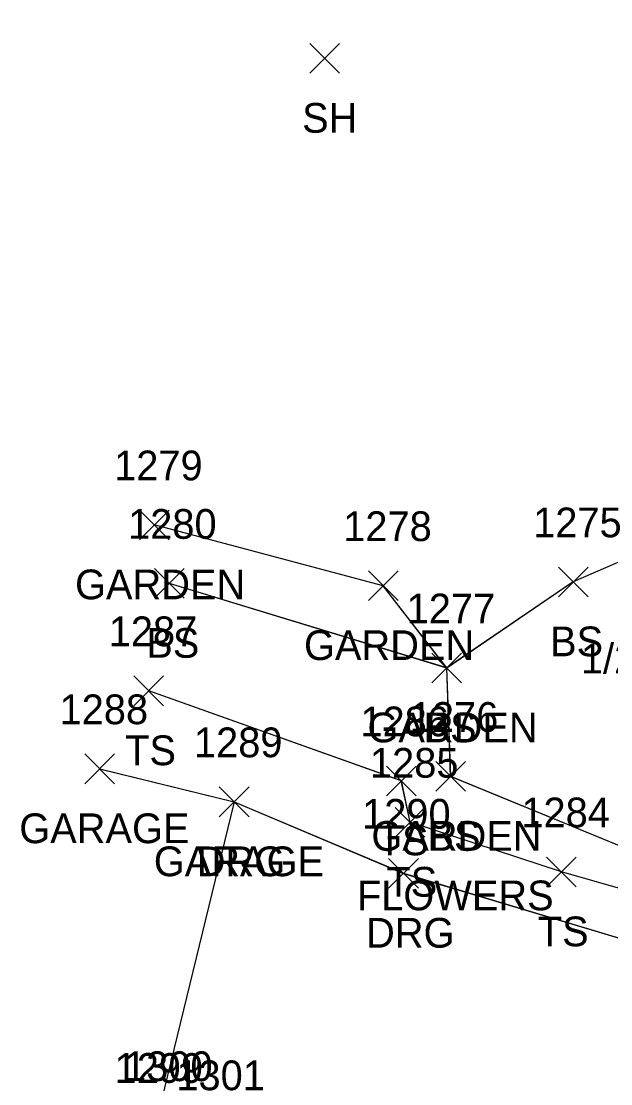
# Model space of a CAD drawing. Extents: x 1554668 to 1563881, y 831386 to 834374.
# Drawn here: x 1561770.7 to 1561810.3, y 833607.6 to 833679 of the extents above; entities that cross this region are included whole.
import ezdxf

# ---------------------------------------------------------------- set-up
doc = ezdxf.new("R2010")
doc.units = 0
for name, color, linetype in [('L_A', 7, 'Continuous'), ('L_C', 7, 'Continuous'), ('L_I', 7, 'Continuous'), ('L_TIC', 7, 'Continuous'), ('LAPB', 7, 'Continuous'), ('LBC', 7, 'Continuous'), ('LELB', 7, 'Continuous'), ('M_C', 7, 'Continuous'), ('R_A', 7, 'Continuous'), ('R_I', 7, 'Continuous'), ('R_TIC', 7, 'Continuous'), ('RDG', 7, 'Continuous')]:
    doc.layers.add(name, color=color, linetype=linetype)

msp = doc.modelspace()

# ---------------------------------------------------------------- linework, layer by layer
at = {"layer": 'L_TIC'}
for points in [[(1561790.057, 833675.514), (1561792.057, 833677.514)], [(1561792.057, 833675.514), (1561790.057, 833677.514)], [(1561778.611, 833644.139), (1561780.611, 833646.139)], [(1561780.611, 833644.139), (1561778.611, 833646.139)], [(1561806.77, 833640.307), (1561808.77, 833642.307)], [(1561808.77, 833640.307), (1561806.77, 833642.307)], [(1561779.627, 833640.207), (1561781.627, 833642.207)], [(1561781.627, 833640.207), (1561779.627, 833642.207)], [(1561794.002, 833640.053), (1561796.002, 833642.053)], [(1561796.002, 833640.053), (1561794.002, 833642.053)], [(1561798.266, 833634.519), (1561800.266, 833636.519)], [(1561800.266, 833634.519), (1561798.266, 833636.519)], [(1561798.266, 833634.519), (1561800.266, 833636.519)], [(1561800.266, 833634.519), (1561798.266, 833636.519)], [(1561778.239, 833632.983), (1561780.239, 833634.983)], [(1561780.239, 833632.983), (1561778.239, 833634.983)], [(1561774.934, 833627.739), (1561776.934, 833629.739)], [(1561776.934, 833627.739), (1561774.934, 833629.739)], [(1561795.213, 833626.925), (1561797.213, 833628.925)], [(1561797.213, 833626.925), (1561795.213, 833628.925)], [(1561798.53, 833627.225), (1561800.53, 833629.225)], [(1561800.53, 833627.225), (1561798.53, 833629.225)], [(1561798.53, 833627.225), (1561800.53, 833629.225)], [(1561800.53, 833627.225), (1561798.53, 833629.225)], [(1561783.977, 833625.518), (1561785.977, 833627.518)], [(1561785.977, 833625.518), (1561783.977, 833627.518)], [(1561795.8, 833624.141), (1561797.8, 833626.141)], [(1561797.8, 833624.141), (1561795.8, 833626.141)], [(1561805.977, 833620.804), (1561807.977, 833622.804)], [(1561807.977, 833620.804), (1561805.977, 833622.804)]]:
    msp.add_lwpolyline(points, dxfattribs=at)
at = {"layer": 'LAPB'}
for points in [[(1561799.534, 833628.228), (1561799.263, 833635.518), (1561795.003, 833641.053), (1561779.611, 833645.139)], [(1561799.534, 833628.228), (1561799.263, 833635.518), (1561795.003, 833641.053), (1561779.611, 833645.139)], [(1561799.534, 833628.228), (1561799.263, 833635.518), (1561795.003, 833641.053), (1561779.611, 833645.139)], [(1561799.53, 833628.225), (1561799.266, 833635.519), (1561795.002, 833641.053), (1561779.611, 833645.139)]]:
    msp.add_lwpolyline(points, dxfattribs=at)
at = {"layer": 'LBC'}
for points in [[(1561775.934, 833628.739), (1561784.977, 833626.518), (1561779.645, 833604.619), (1561778.909, 833601.945)], [(1561775.938, 833628.741), (1561784.978, 833626.518), (1561779.644, 833604.618), (1561778.911, 833601.947)], [(1561775.938, 833628.741), (1561784.978, 833626.518), (1561779.644, 833604.618), (1561778.911, 833601.947)], [(1561775.938, 833628.741), (1561784.978, 833626.518), (1561779.644, 833604.618), (1561778.911, 833601.947)]]:
    msp.add_lwpolyline(points, dxfattribs=at)
at = {"layer": 'LELB'}
for points in [[(1561848.403, 833772.22), (1561859.088, 833762.967), (1561862.218, 833760.08), (1561856.867, 833725.001), (1561850.329, 833695.923), (1561848.444, 833676.048), (1561846.147, 833662.128), (1561840.876, 833636.676), (1561837.465, 833618.453), (1561834.406, 833616.246), (1561820.201, 833618.031), (1561806.977, 833621.804), (1561796.8, 833625.141), (1561796.213, 833627.925), (1561779.239, 833633.983)], [(1561848.403, 833772.219), (1561859.088, 833762.966), (1561862.218, 833760.077), (1561856.867, 833725.003), (1561850.329, 833695.921), (1561848.444, 833676.044), (1561846.147, 833662.13), (1561840.875, 833636.672), (1561837.466, 833618.455), (1561834.407, 833616.245), (1561820.203, 833618.032), (1561806.976, 833621.803), (1561796.804, 833625.143), (1561796.218, 833627.927), (1561779.24, 833633.983)], [(1561848.403, 833772.219), (1561859.088, 833762.966), (1561862.218, 833760.077), (1561856.867, 833725.003), (1561850.329, 833695.921), (1561848.444, 833676.044), (1561846.147, 833662.13), (1561840.875, 833636.672), (1561837.466, 833618.455), (1561834.407, 833616.245), (1561820.203, 833618.032), (1561806.976, 833621.803), (1561796.804, 833625.143), (1561796.218, 833627.927), (1561779.24, 833633.983)], [(1561848.403, 833772.219), (1561859.088, 833762.966), (1561862.218, 833760.077), (1561856.867, 833725.003), (1561850.329, 833695.921), (1561848.444, 833676.044), (1561846.147, 833662.13), (1561840.875, 833636.672), (1561837.466, 833618.455), (1561834.407, 833616.245), (1561820.203, 833618.032), (1561806.976, 833621.803), (1561796.804, 833625.143), (1561796.218, 833627.927), (1561779.24, 833633.983)], [(1561838.605, 833677.998), (1561829.617, 833668.653), (1561823.684, 833659.704), (1561821.485, 833647.25), (1561807.767, 833641.305), (1561799.263, 833635.518), (1561780.626, 833641.206)], [(1561838.605, 833677.998), (1561829.617, 833668.653), (1561823.684, 833659.704), (1561821.485, 833647.25), (1561807.767, 833641.305), (1561799.263, 833635.518), (1561780.626, 833641.206)], [(1561838.605, 833677.998), (1561829.617, 833668.653), (1561823.684, 833659.704), (1561821.485, 833647.25), (1561807.767, 833641.305), (1561799.263, 833635.518), (1561780.626, 833641.206)], [(1561838.604, 833678.002), (1561829.616, 833668.654), (1561823.684, 833659.704), (1561821.488, 833647.251), (1561807.77, 833641.307), (1561799.266, 833635.519), (1561780.627, 833641.207)], [(1561848.444, 833676.048), (1561844.799, 833670.578), (1561841.627, 833661.304), (1561838.317, 833640.017), (1561835.978, 833633.418), (1561832.86, 833623.022), (1561827.701, 833621.133), (1561820.726, 833621.391), (1561813.002, 833622.688), (1561799.53, 833628.225)], [(1561848.444, 833676.044), (1561844.8, 833670.576), (1561841.628, 833661.304), (1561838.319, 833640.02), (1561835.977, 833633.414), (1561832.862, 833623.026), (1561827.701, 833621.134), (1561820.728, 833621.393), (1561813.002, 833622.688), (1561799.534, 833628.228)], [(1561848.444, 833676.044), (1561844.8, 833670.576), (1561841.628, 833661.304), (1561838.319, 833640.02), (1561835.977, 833633.414), (1561832.862, 833623.026), (1561827.701, 833621.134), (1561820.728, 833621.393), (1561813.002, 833622.688), (1561799.534, 833628.228)], [(1561848.444, 833676.044), (1561844.8, 833670.576), (1561841.628, 833661.304), (1561838.319, 833640.02), (1561835.977, 833633.414), (1561832.862, 833623.026), (1561827.701, 833621.134), (1561820.728, 833621.393), (1561813.002, 833622.688), (1561799.534, 833628.228)]]:
    msp.add_lwpolyline(points, dxfattribs=at)
at = {"layer": 'R_TIC'}
for points in [[(1561783.977, 833625.518), (1561785.977, 833627.518)], [(1561785.977, 833625.518), (1561783.977, 833627.518)], [(1561795.358, 833620.711), (1561797.358, 833622.711)], [(1561797.358, 833620.711), (1561795.358, 833622.711)]]:
    msp.add_lwpolyline(points, dxfattribs=at)
at = {"layer": 'RDG'}
for points in [[(1561784.977, 833626.518), (1561796.358, 833621.711), (1561816.548, 833615.654), (1561833.959, 833612.712), (1561838.87, 833614.302)], [(1561784.978, 833626.518), (1561796.356, 833621.71), (1561816.55, 833615.656), (1561833.96, 833612.712), (1561838.871, 833614.304)], [(1561784.978, 833626.518), (1561796.356, 833621.71), (1561816.55, 833615.656), (1561833.96, 833612.712), (1561838.871, 833614.304)], [(1561784.978, 833626.518), (1561796.356, 833621.71), (1561816.55, 833615.656), (1561833.96, 833612.712), (1561838.871, 833614.304)]]:
    msp.add_lwpolyline(points, dxfattribs=at)

# ---------------------------------------------------------------- texts
at = {"layer": 'L_A'}
for s, p in [('SH', (1561789.545, 833671.514)), ('GARDEN', (1561774.28, 833640.139)), ('BS', (1561779.068, 833636.207)), ('GARDEN', (1561789.671, 833636.053)), ('BS', (1561806.211, 833636.307)), ('GARDEN', (1561793.936, 833630.519)), ('BS', (1561797.707, 833630.519)), ('TS', (1561777.648, 833628.983)), ('GARAGE', (1561770.532, 833623.739)), ('GARDEN', (1561794.199, 833623.225)), ('BS', (1561797.971, 833623.225)), ('TS', (1561794.623, 833622.925)), ('GARAGE', (1561779.576, 833621.518)), ('TS', (1561795.21, 833620.141)), ('TS', (1561805.386, 833616.804))]:
    msp.add_text(s, height=2, dxfattribs=at).set_placement(p)
at = {"layer": 'L_C'}
msp.add_text('FLOWERS', height=2, dxfattribs=at).set_placement((1561793.23, 833619.225))
at = {"layer": 'L_I'}
for s, p in [('1279', (1561776.91, 833648.139)), ('1280', (1561777.848, 833644.207)), ('1278', (1561792.309, 833644.053)), ('1275', (1561805.077, 833644.307)), ('1277', (1561796.573, 833638.519)), ('1277', (1561796.573, 833638.519)), ('1287', (1561776.546, 833636.983)), ('1288', (1561773.241, 833631.739)), ('1276', (1561796.782, 833631.225)), ('1276', (1561796.782, 833631.225)), ('1286', (1561793.465, 833630.925)), ('1289', (1561782.276, 833629.518)), ('1285', (1561794.107, 833628.141)), ('1284', (1561804.284, 833624.804)), ('1299', (1561776.944, 833607.619))]:
    msp.add_text(s, height=2, dxfattribs=at).set_placement(p)
at = {"layer": 'M_C'}
msp.add_text('1/2" REBAR, 2\' ABOVE GROUND,', height=2, dxfattribs=at).set_placement((1561808.287, 833635.152))
at = {"layer": 'R_A'}
for p in [(1561782.465, 833621.518), (1561793.846, 833616.711)]:
    msp.add_text('DRG', height=2, dxfattribs=at).set_placement(p)
at = {"layer": 'R_I'}
for s, p in [('1289', (1561782.276, 833629.518)), ('1290', (1561793.578, 833624.711)), ('1299', (1561776.944, 833607.619)), ('1300', (1561777.577, 833607.737)), ('1301', (1561781.093, 833607.125)), ('1301', (1561781.093, 833607.125))]:
    msp.add_text(s, height=2, dxfattribs=at).set_placement(p)

doc.saveas('drawing.dxf')
